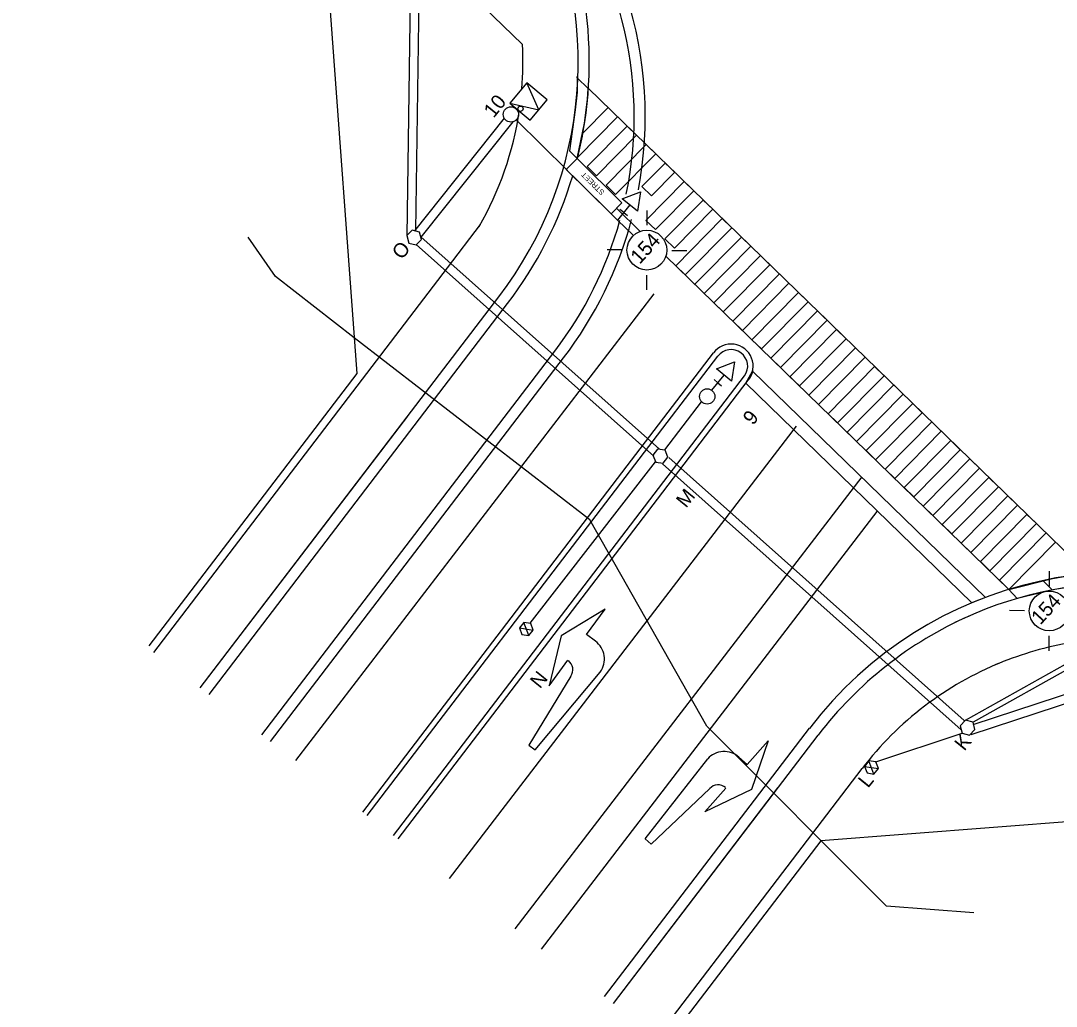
# Model space of a CAD drawing. Extents: x 592613 to 600223, y 4837996 to 4840103.
# Drawn here: x 592974.48 to 593021.3, y 4839279.73 to 4839324.28 of the extents above; entities that cross this region are included whole.
import ezdxf

# ---------------------------------------------------------------- set-up
doc = ezdxf.new("R2010")
doc.units = 0
for name, color, linetype in [('ENG_CURB-BACK', 7, 'Continuous'), ('ENG_CURBSTOP', 7, 'Continuous'), ('ENG_EPAVT', 7, 'Continuous'), ('ENG_LANEWAY', 7, 'Continuous'), ('ENG_SH_RIPRAP', 7, 'Continuous'), ('ENG_SIDEWALK', 7, 'Continuous'), ('ENG_TX_TITLEBLOCK', 7, 'Continuous'), ('Level 12', 7, 'Continuous'), ('Level 9', 7, 'Continuous'), ('PMK_LANE', 7, 'Continuous'), ('ROW_ENG_ROW', 7, 'Continuous'), ('ROW_ENG_ROW BO', 7, 'Continuous'), ('TCS_100mm-NEW', 7, 'Continuous'), ('TCS_50mm-NEW', 7, 'Continuous'), ('TCS_ELEC-CHAMBER-NEW', 7, 'Continuous'), ('TCS_LUMINAIRE-NEW', 7, 'Continuous'), ('TCS_POLE-NEW', 7, 'Continuous'), ('TCS_PUSHBUTTON', 7, 'Continuous'), ('TCS_SIGN', 7, 'Continuous'), ('TCS_SIGNALHEAD', 7, 'Continuous')]:
    doc.layers.add(name, color=color, linetype=linetype)

msp = doc.modelspace()

# ---------------------------------------------------------------- linework, layer by layer
at = {"layer": 'ENG_CURB-BACK'}
for p, q in [((592982.6, 4839294.121), (592996.101, 4839311.803)), ((592985.382, 4839291.997), (592998.629, 4839309.347)), ((593002.255, 4839304.209), (593006.002, 4839309.117)), ((593003.128, 4839302.881), (593007.211, 4839308.228)), ((592990.151, 4839288.356), (593002.255, 4839304.209)), ((592991.343, 4839287.446), (593003.125, 4839302.877)), ((593001.278, 4839279.86), (593010.54, 4839291.99)), ((593003.266, 4839278.343), (593012.528, 4839290.474))]:
    msp.add_line(p, q, dxfattribs=at)
for centre, radius, start, end in [((592984.72, 4839319.967), 17.5, 348.3699, 40.5041), ((592982.191, 4839322.423), 17.5, 322.6377, 27.9119), ((592984.72, 4839319.967), 17.5, 322.6377, 344.4), ((593006.601, 4839308.664), 0.75, 324.4115, 142.9443), ((593024.449, 4839281.37), 17.5, 62.8455, 116.2063), ((593024.449, 4839281.37), 17.5, 113.9004, 142.6377)]:
    msp.add_arc(centre, radius, start, end, dxfattribs=at)
at = {"layer": 'ENG_CURBSTOP'}
msp.add_line((593021.121, 4839298.551), (593020.688, 4839298.973), dxfattribs=at)
for points in [[(592999.289, 4839318.404), (592999.646, 4839318.058), (592999.977, 4839319.652), (593000.111, 4839320.728), (593000.143, 4839321.215), (593000.143, 4839321.215), (592999.636, 4839321.707), (592999.638, 4839321.762), (592999.638, 4839321.052), (592999.557, 4839320.258)], [(593024.375, 4839298.87), (593023.359, 4839298.836), (593022.22, 4839298.728), (593021.245, 4839298.574), (593019.537, 4839298.161), (593019.155, 4839298.567), (593021.133, 4839299.062), (593021.663, 4839299.153), (593022.119, 4839299.219), (593022.783, 4839299.293), (593023.495, 4839299.345), (593024.042, 4839299.366), (593024.286, 4839299.369)]]:
    msp.add_lwpolyline(points, close=True, dxfattribs=at)
at = {"layer": 'ENG_EPAVT'}
for p, q in [((592982.998, 4839293.818), (592996.498, 4839311.499)), ((592985.779, 4839291.694), (592999.026, 4839309.043)), ((593002.103, 4839304.421), (593005.803, 4839309.267)), ((593003.274, 4839302.66), (593007.379, 4839308.037)), ((592989.952, 4839288.508), (593002.098, 4839304.415)), ((592991.542, 4839287.294), (593003.274, 4839302.66)), ((593000.881, 4839280.163), (593010.143, 4839292.294))]:
    msp.add_line(p, q, dxfattribs=at)
for centre, radius, start, end in [((592984.72, 4839319.967), 18, 349.35, 45.8289), ((592982.191, 4839322.423), 18, 345.9453, 28.6887), ((592982.191, 4839322.423), 18, 322.6377, 343.3725), ((592984.72, 4839319.967), 18, 322.6377, 344.9839), ((593006.599, 4839308.666), 1, 320.9502, 142.7929), ((593006.599, 4839308.666), 1, 320.9502, 142.7929), ((593006.601, 4839308.664), 1, 321.1016, 142.9443), ((593024.449, 4839281.37), 18, 62.5135, 142.6377)]:
    msp.add_arc(centre, radius, start, end, dxfattribs=at)
at = {"layer": 'ENG_LANEWAY'}
for p, q in [((592986.922, 4839290.837), (593003.123, 4839311.94)), ((592993.863, 4839285.509), (593009.559, 4839305.953)), ((592996.838, 4839283.225), (593012.533, 4839303.67)), ((592998.027, 4839282.312), (593013.211, 4839302.09))]:
    msp.add_line(p, q, dxfattribs=at)
at = {"layer": 'ENG_SH_RIPRAP'}
msp.add_lwpolyline([(593017.573, 4839283.959), (593013.626, 4839284.25), (593005.501, 4839292.394), (593000.214, 4839301.724), (592989.561, 4839309.954), (592985.998, 4839312.719), (592984.767, 4839314.492)], dxfattribs=at)
at = {"layer": 'ENG_SIDEWALK'}
for p, q in [((592997.171, 4839323.207), (592971.051, 4839348.581)), ((592993.775, 4839313.119), (592995.266, 4839315.071)), ((592980.497, 4839295.727), (592993.775, 4839313.119)), ((592982.6, 4839294.121), (592991.979, 4839306.404)), ((593001.278, 4839279.86), (593008.717, 4839289.602))]:
    msp.add_line(p, q, dxfattribs=at)
for centre, start, end in [((592982.191, 4839322.423), 355.3661, 2.9955), ((592982.191, 4839322.423), 330.2382, 351.4856), ((593024.449, 4839281.37), 100.1986, 113.33), ((593024.449, 4839281.37), 112.093, 142.6377)]:
    msp.add_arc(centre, 15, start, end, dxfattribs=at)
at = {"layer": 'Level 12'}
for p, q in [((593000.911, 4839297.688), (592998.917, 4839296.48)), ((593000.065, 4839296.529), (593000.911, 4839297.688)), ((592998.917, 4839296.48), (592998.373, 4839294.212)), ((593000.465, 4839296.237), (593000.065, 4839296.529)), ((592998.373, 4839294.212), (592999.219, 4839295.371)), ((592999.352, 4839294.655), (592997.449, 4839291.54)), ((592997.745, 4839291.323), (593000.683, 4839294.84)), ((593007.324, 4839290.663), (593008.279, 4839291.733)), ((593008.279, 4839291.733), (593007.516, 4839289.531)), ((592997.449, 4839291.54), (592997.745, 4839291.323)), ((593002.721, 4839287.302), (593005.542, 4839290.913)), ((593006.954, 4839290.993), (593007.324, 4839290.663)), ((593005.641, 4839289.573), (593002.994, 4839287.059)), ((593005.414, 4839288.523), (593006.369, 4839289.594)), ((593007.516, 4839289.531), (593005.414, 4839288.523)), ((593002.994, 4839287.059), (593002.721, 4839287.302))]:
    msp.add_line(p, q, dxfattribs=at)
for centre, radius, start, end in [((592999.875, 4839295.429), 1, 323.8506, 53.8728), ((592998.948, 4839294.95), 0.5, 323.8443, 53.8679), ((593006.288, 4839290.247), 1, 48.242, 138.2642), ((593006.014, 4839289.24), 0.5, 48.2469, 138.2706)]:
    msp.add_arc(centre, radius, start, end, dxfattribs=at)
at = {"layer": 'PMK_LANE'}
for p, q in [((593000.151, 4839321.221), (593022.099, 4839299.906)), ((593001.039, 4839320.358), (592999.902, 4839319.206)), ((593001.47, 4839319.94), (593001.039, 4839320.358)), ((592999.669, 4839318.116), (593001.47, 4839319.94)), ((593001.9, 4839319.522), (593000.091, 4839317.69)), ((593002.331, 4839319.104), (593001.9, 4839319.522)), ((593000.522, 4839317.272), (593002.331, 4839319.104)), ((593002.761, 4839318.686), (593000.947, 4839316.849)), ((593003.191, 4839318.268), (593002.761, 4839318.686)), ((593001.377, 4839316.431), (593003.191, 4839318.268)), ((593000.091, 4839317.69), (593000.522, 4839317.272)), ((593003.622, 4839317.85), (593002.568, 4839316.783)), ((593004.052, 4839317.432), (593003.622, 4839317.85)), ((593004.483, 4839317.014), (593002.748, 4839315.257)), ((593002.998, 4839316.365), (593004.052, 4839317.432)), ((593004.913, 4839316.596), (593004.483, 4839317.014)), ((593000.947, 4839316.849), (593001.377, 4839316.431)), ((593002.568, 4839316.783), (593002.998, 4839316.365)), ((593003.179, 4839314.839), (593004.913, 4839316.596)), ((593005.344, 4839316.178), (593003.604, 4839314.417)), ((593005.774, 4839315.76), (593005.344, 4839316.178)), ((593001.42, 4839315.807), (593002.496, 4839314.762)), ((593004.035, 4839313.998), (593005.774, 4839315.76)), ((593002.748, 4839315.257), (593003.179, 4839314.839)), ((593006.204, 4839315.342), (593004.097, 4839313.207)), ((593006.635, 4839314.924), (593006.204, 4839315.342)), ((593004.527, 4839312.789), (593006.635, 4839314.924)), ((593003.604, 4839314.417), (593004.035, 4839313.998)), ((593007.065, 4839314.506), (593004.958, 4839312.371)), ((593007.496, 4839314.088), (593007.065, 4839314.506)), ((593005.388, 4839311.953), (593007.496, 4839314.088)), ((593003.652, 4839313.639), (593019.162, 4839298.576)), ((593007.926, 4839313.67), (593005.818, 4839311.535)), ((593006.249, 4839311.117), (593008.357, 4839313.252)), ((593008.357, 4839313.252), (593007.926, 4839313.67)), ((593004.097, 4839313.207), (593004.527, 4839312.789)), ((593008.787, 4839312.834), (593006.679, 4839310.699)), ((593009.218, 4839312.416), (593008.787, 4839312.834)), ((593004.958, 4839312.371), (593005.388, 4839311.953)), ((593007.11, 4839310.281), (593009.218, 4839312.416)), ((593009.648, 4839311.998), (593007.54, 4839309.863)), ((593010.078, 4839311.58), (593009.648, 4839311.998)), ((593005.818, 4839311.535), (593006.249, 4839311.117)), ((593007.971, 4839309.445), (593010.078, 4839311.58)), ((593010.509, 4839311.162), (593008.401, 4839309.027)), ((593010.939, 4839310.744), (593010.509, 4839311.162)), ((593006.679, 4839310.699), (593007.11, 4839310.281)), ((593008.832, 4839308.609), (593010.939, 4839310.744)), ((593011.37, 4839310.326), (593009.262, 4839308.191)), ((593011.8, 4839309.908), (593011.37, 4839310.326)), ((593007.54, 4839309.863), (593007.971, 4839309.445)), ((593009.692, 4839307.773), (593011.8, 4839309.908)), ((593012.231, 4839309.49), (593010.123, 4839307.355)), ((593012.661, 4839309.072), (593012.231, 4839309.49)), ((593008.401, 4839309.027), (593008.832, 4839308.609)), ((593010.553, 4839306.937), (593012.661, 4839309.072)), ((593013.092, 4839308.654), (593010.984, 4839306.519)), ((593013.522, 4839308.236), (593013.092, 4839308.654)), ((593007.574, 4839308.436), (593018.1, 4839298.213)), ((593009.262, 4839308.191), (593009.692, 4839307.773)), ((593011.414, 4839306.101), (593013.522, 4839308.236)), ((593007.271, 4839307.894), (593017.489, 4839297.97)), ((593013.952, 4839307.818), (593011.845, 4839305.683)), ((593014.383, 4839307.4), (593013.952, 4839307.818)), ((593010.123, 4839307.355), (593010.553, 4839306.937)), ((593012.275, 4839305.265), (593014.383, 4839307.4)), ((593014.813, 4839306.982), (593012.705, 4839304.847)), ((593015.244, 4839306.563), (593014.813, 4839306.982)), ((593010.984, 4839306.519), (593011.414, 4839306.101)), ((593013.136, 4839304.429), (593015.244, 4839306.563)), ((593015.674, 4839306.145), (593013.566, 4839304.011)), ((593016.105, 4839305.727), (593015.674, 4839306.145)), ((593011.845, 4839305.683), (593012.275, 4839305.265)), ((593013.997, 4839303.593), (593016.105, 4839305.727)), ((593016.535, 4839305.309), (593014.427, 4839303.175)), ((593016.965, 4839304.891), (593016.535, 4839305.309)), ((593012.705, 4839304.847), (593013.136, 4839304.429)), ((593014.858, 4839302.756), (593016.965, 4839304.891)), ((593017.396, 4839304.473), (593015.288, 4839302.338)), ((593017.826, 4839304.055), (593017.396, 4839304.473)), ((593013.566, 4839304.011), (593013.997, 4839303.593)), ((593015.719, 4839301.92), (593017.826, 4839304.055)), ((593018.257, 4839303.637), (593016.149, 4839301.502)), ((593018.687, 4839303.219), (593018.257, 4839303.637)), ((593014.427, 4839303.175), (593014.858, 4839302.756)), ((593016.579, 4839301.084), (593018.687, 4839303.219)), ((593019.118, 4839302.801), (593017.01, 4839300.666)), ((593019.548, 4839302.383), (593019.118, 4839302.801)), ((593015.288, 4839302.338), (593015.719, 4839301.92)), ((593017.44, 4839300.248), (593019.548, 4839302.383)), ((593019.979, 4839301.965), (593017.871, 4839299.83)), ((593018.301, 4839299.412), (593020.409, 4839301.547)), ((593020.409, 4839301.547), (593019.979, 4839301.965)), ((593016.149, 4839301.502), (593016.579, 4839301.084)), ((593020.839, 4839301.129), (593018.732, 4839298.994)), ((593021.27, 4839300.711), (593020.839, 4839301.129)), ((593017.01, 4839300.666), (593017.44, 4839300.248)), ((593019.162, 4839298.576), (593021.27, 4839300.711)), ((593017.871, 4839299.83), (593018.301, 4839299.412)), ((593018.732, 4839298.994), (593019.162, 4839298.576))]:
    msp.add_line(p, q, dxfattribs=at)
msp.add_lwpolyline([(593007.271, 4839307.894), (593007.574, 4839308.436), (593018.1, 4839298.213), (593017.489, 4839297.97)], close=True, dxfattribs=at)
msp.add_arc((592982.191, 4839322.423), 18, 346.1571, 349.7059, dxfattribs=at)
at = {"layer": 'ROW_ENG_ROW'}
for p, q in [((592988.026, 4839330.697), (592989.681, 4839308.33)), ((593031.168, 4839288.785), (593010.654, 4839287.203))]:
    msp.add_line(p, q, dxfattribs=at)
at = {"layer": 'ROW_ENG_ROW BO'}
for p, q in [((592989.681, 4839308.33), (592980.281, 4839296.018)), ((593010.654, 4839287.203), (593003.395, 4839277.695))]:
    msp.add_line(p, q, dxfattribs=at)
at = {"layer": 'TCS_100mm-NEW'}
for p, q in [((592992.203, 4839332.991), (592991.935, 4839314.564)), ((592992.3, 4839314.78), (592996.358, 4839319.872)), ((592992.365, 4839314.17), (593003.113, 4839304.6)), ((593003.6, 4839304.888), (593005.268, 4839307.048)), ((593003.501, 4839304.254), (593017.009, 4839292.228)), ((593017.452, 4839292.021), (593029.189, 4839295.876)), ((593022.229, 4839295.188), (593017.538, 4839292.568))]:
    msp.add_line(p, q, dxfattribs=at)
at = {"layer": 'TCS_50mm-NEW'}
for p, q in [((592992.59, 4839332.818), (592992.338, 4839314.788)), ((592992.593, 4839314.506), (592996.744, 4839319.714)), ((592992.58, 4839314.513), (593003.364, 4839304.912)), ((592997.522, 4839297.047), (593003.184, 4839304.345)), ((593003.788, 4839304.534), (593017.139, 4839292.648)), ((593017.538, 4839292.471), (593029.064, 4839296.256)), ((593017.204, 4839292.658), (593022.1, 4839295.402)), ((593013.147, 4839290.773), (593017.049, 4839292.079))]:
    msp.add_line(p, q, dxfattribs=at)
at = {"layer": 'TCS_ELEC-CHAMBER-NEW'}
for p, q in [((592992.178, 4839314.812), (592991.934, 4839314.568)), ((592992.512, 4839314.723), (592992.178, 4839314.812)), ((592992.602, 4839314.389), (592992.512, 4839314.723)), ((592991.934, 4839314.568), (592992.024, 4839314.234)), ((592992.024, 4839314.234), (592992.357, 4839314.145)), ((592992.357, 4839314.145), (592992.602, 4839314.389)), ((593003.272, 4839304.921), (593003.062, 4839304.647)), ((593003.615, 4839304.875), (593003.272, 4839304.921)), ((593003.747, 4839304.556), (593003.615, 4839304.875)), ((593003.062, 4839304.647), (593003.194, 4839304.328)), ((593003.194, 4839304.328), (593003.536, 4839304.282)), ((593003.536, 4839304.282), (593003.747, 4839304.556)), ((592997.229, 4839297.084), (592997.028, 4839296.836)), ((592997.028, 4839296.836), (592997.658, 4839296.737)), ((592997.028, 4839296.836), (592997.143, 4839296.538)), ((592997.458, 4839296.489), (592997.229, 4839297.084)), ((592997.544, 4839297.034), (592997.229, 4839297.084)), ((592997.658, 4839296.737), (592997.544, 4839297.034)), ((592997.143, 4839296.538), (592997.458, 4839296.489)), ((592997.458, 4839296.489), (592997.658, 4839296.737)), ((593017.204, 4839292.658), (593016.96, 4839292.413)), ((593017.538, 4839292.568), (593017.204, 4839292.658)), ((593016.96, 4839292.413), (593017.049, 4839292.079)), ((593017.383, 4839291.99), (593017.627, 4839292.234)), ((593017.627, 4839292.234), (593017.538, 4839292.568)), ((593017.049, 4839292.079), (593017.383, 4839291.99)), ((593012.832, 4839290.823), (593012.631, 4839290.575)), ((593013.061, 4839290.227), (593012.832, 4839290.823)), ((593013.147, 4839290.773), (593012.832, 4839290.823)), ((593013.261, 4839290.475), (593013.147, 4839290.773)), ((593012.631, 4839290.575), (593013.261, 4839290.475)), ((593012.631, 4839290.575), (593012.746, 4839290.277)), ((593013.061, 4839290.227), (593013.261, 4839290.475)), ((593012.746, 4839290.277), (593013.061, 4839290.227))]:
    msp.add_line(p, q, dxfattribs=at)
at = {"layer": 'TCS_LUMINAIRE-NEW'}
for p, q in [((592996.891, 4839319.804), (592999.205, 4839317.51)), ((592999.434, 4839317.284), (593001.467, 4839315.27)), ((593002.805, 4839315.037), (593002.812, 4839315.712)), ((593001.467, 4839315.27), (593002.192, 4839314.581)), ((593001.67, 4839313.923), (593000.994, 4839313.93)), ((593003.918, 4839313.901), (593004.594, 4839313.894)), ((593002.783, 4839312.788), (593002.776, 4839312.112)), ((593020.995, 4839298.725), (593021.002, 4839299.4)), ((593019.86, 4839297.611), (593019.184, 4839297.618)), ((593020.973, 4839296.476), (593020.966, 4839295.8))]:
    msp.add_line(p, q, dxfattribs=at)
for centre in [(593002.794, 4839313.912), (593020.984, 4839297.6)]:
    msp.add_circle(centre, 0.9, dxfattribs=at)
at = {"layer": 'TCS_POLE-NEW'}
for centre in [(592996.645, 4839320.047), (593005.52, 4839307.296)]:
    msp.add_circle(centre, 0.346, dxfattribs=at)
at = {"layer": 'TCS_PUSHBUTTON'}
msp.add_circle((592997.082, 4839320.304), 0.12, dxfattribs=at)
at = {"layer": 'TCS_SIGN'}
msp.add_lwpolyline([(593001.172, 4839315.556), (592999.15, 4839317.557), (592999.646, 4839318.058), (593001.668, 4839316.057)], close=True, dxfattribs=at)
at = {"layer": 'TCS_SIGNALHEAD'}
for p, q in [((592998.288, 4839320.712), (592997.367, 4839321.48)), ((592996.598, 4839320.558), (592997.52, 4839319.79)), ((592997.52, 4839319.79), (592998.288, 4839320.712)), ((593001.682, 4839316.233), (593002.506, 4839316.548)), ((593002.506, 4839316.548), (593002.366, 4839315.676)), ((593002.366, 4839315.676), (593001.682, 4839316.233)), ((593002.024, 4839315.955), (593001.467, 4839315.27)), ((593001.745, 4839315.613), (593001.574, 4839315.752)), ((593001.745, 4839315.613), (593001.916, 4839315.473)), ((593005.937, 4839308.541), (593006.761, 4839308.856)), ((593006.621, 4839307.984), (593005.937, 4839308.541)), ((593006.761, 4839308.856), (593006.621, 4839307.984)), ((593006.278, 4839308.263), (593005.721, 4839307.578)), ((593006, 4839307.92), (593005.829, 4839308.059)), ((593006, 4839307.92), (593006.171, 4839307.781))]:
    msp.add_line(p, q, dxfattribs=at)
for points in [[(592997.367, 4839321.48), (592996.598, 4839320.558), (592997.904, 4839320.251), (592997.904, 4839320.251)], [(593002.366, 4839315.676), (593001.682, 4839316.233), (593002.506, 4839316.548), (593002.506, 4839316.548)], [(593006.621, 4839307.984), (593005.937, 4839308.541), (593006.761, 4839308.856), (593006.761, 4839308.856)]]:
    msp.add_lwpolyline(points, close=True, dxfattribs=at)

# ---------------------------------------------------------------- texts
at = {"layer": 'ENG_TX_TITLEBLOCK'}
msp.add_text('AS CONSTRUCTED', height=4.52865, rotation=50.906, dxfattribs=at).set_placement((592943.824, 4839296.556))
at = {"layer": 'Level 9'}
msp.add_text('154', height=0.65, rotation=47.2608, dxfattribs=at).set_placement((593002.468, 4839313.245))
at = {"layer": 'TCS_ELEC-CHAMBER-NEW'}
for s, p in [('O', (592991.716, 4839313.446)), ('M', (593004.562, 4839302.223)), ('N', (592997.96, 4839294.053)), ('K', (593017.146, 4839291.237)), ('L', (593012.79, 4839289.561))]:
    msp.add_text(s, height=0.65, rotation=51.0574, dxfattribs=at).set_placement(p)
at = {"layer": 'TCS_LUMINAIRE-NEW'}
for p in [(593002.465, 4839313.25), (593020.584, 4839296.939)]:
    msp.add_text('154', height=0.65, rotation=47.2608, dxfattribs=at).set_placement(p)
at = {"layer": 'TCS_POLE-NEW'}
for s, p in [('10', (592995.866, 4839319.855)), ('9', (593007.584, 4839305.961))]:
    msp.add_text(s, height=0.65, rotation=51.0574, dxfattribs=at).set_placement(p)
at = {"layer": 'TCS_SIGN'}
msp.add_text('STREET', height=0.2407, rotation=135.3025, dxfattribs=at).set_placement((593000.901, 4839316.547))

doc.saveas('drawing.dxf')
